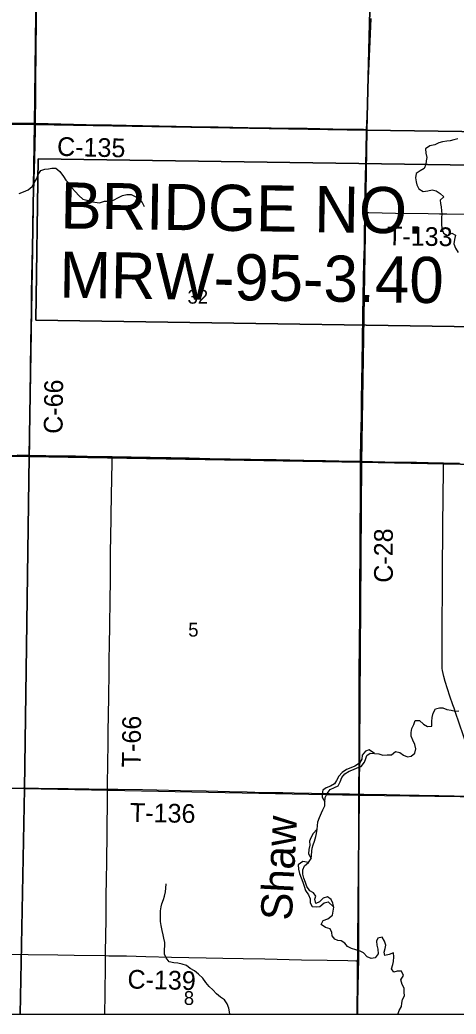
# Model space of a CAD drawing. Extents: x 0 to 34, y 0 to 22.
# Drawn here: x 3.955 to 5.278, y 14 to 17.017 of the extents above; entities that cross this region are included whole.
import ezdxf

# ---------------------------------------------------------------- set-up
doc = ezdxf.new("R2010")
doc.units = 0
for name, color, linetype in [('Default', 7, 'Continuous'), ('GM_X_City_Street', 7, 'Continuous'), ('GM_X_County_Road_Text', 7, 'Continuous'), ('GM_X_Interchange_Ramps', 7, 'Continuous'), ('GM_X_Major_River_Text', 7, 'Continuous'), ('GM_X_Minor_River', 7, 'Continuous'), ('GM_X_Minor_River_Text', 7, 'Continuous'), ('GM_X_Rail_Line', 7, 'Continuous'), ('GM_X_Section', 7, 'Continuous'), ('GM_X_Unincorporated_Location', 7, 'Continuous'), ('SH_Border', 7, 'Continuous'), ('SH_Cut_Line', 7, 'Continuous'), ('SH_Text', 7, 'Continuous')]:
    doc.layers.add(name, color=color, linetype=linetype)

msp = doc.modelspace()

# ---------------------------------------------------------------- linework, layer by layer
at = {"layer": 'Default'}
for points in [[(3.9466, 15.6957), (3.9843, 15.695), (4.0335, 15.6941), (4.077, 15.6934), (4.1236, 15.6926), (4.1951, 15.6914), (4.2351, 15.6907), (4.3504, 15.6887), (4.4125, 15.6874), (4.4684, 15.6866), (4.5305, 15.6851), (4.6547, 15.6829), (4.692, 15.6822), (4.7324, 15.6816), (4.8163, 15.68), (4.8815, 15.6788), (4.9622, 15.6771), (4.9878, 15.6767), (5.0616, 15.6752), (5.1579, 15.6733), (5.2294, 15.6716), (5.2396, 15.6714), (5.2884, 15.6704)], [(5.2884, 15.6704), (5.2396, 15.6714), (5.2294, 15.6716), (5.1579, 15.6733), (5.0616, 15.6752), (4.9878, 15.6767), (4.9622, 15.6771), (4.8815, 15.6788), (4.8163, 15.68), (4.7324, 15.6816), (4.692, 15.6822), (4.6547, 15.6829), (4.5305, 15.6851), (4.4684, 15.6866), (4.4125, 15.6874), (4.3504, 15.6887), (4.2351, 15.6907), (4.1951, 15.6914), (4.1236, 15.6926), (4.077, 15.6934), (4.0335, 15.6941), (3.9843, 15.695), (3.9466, 15.6957)], [(2.9377, 14), (7.9275, 14)]]:
    msp.add_lwpolyline(points, dxfattribs=at)
for points in [[(2.9554, 14), (3.9561, 14), (3.9687, 14.6839), (3.2537, 14.69), (2.9712, 14.7039), (2.9687, 14.7038)], [(3.9561, 14), (4.9774, 14), (4.9836, 14.6638), (3.9687, 14.6839)], [(4.9774, 14), (5.9688, 14), (5.9788, 14.6503), (4.9836, 14.6638)]]:
    msp.add_lwpolyline(points, close=True, dxfattribs=at)
at = {"layer": 'GM_X_City_Street'}
for points in [[(4.0025, 16.7029), (4.0027, 16.7213), (4.0033, 16.7679), (4.0037, 16.8145), (4.0046, 16.9356), (4.0053, 17.004), (4.0062, 17.0972), (4.0066, 17.15), (4.0072, 17.1841), (4.0076, 17.2059), (4.0077, 17.2431), (4.0078, 17.3053), (4.0084, 17.3612), (4.0087, 17.4016), (4.0091, 17.4326), (4.0093, 17.4823), (4.0097, 17.5258), (4.0103, 17.5848), (4.0105, 17.619), (4.0108, 17.6594), (4.0111, 17.7107)], [(5.0063, 16.6842), (5.0086, 16.742), (5.0115, 16.8165), (5.0144, 16.8848), (5.0161, 16.9283), (5.018, 16.9749), (5.0198, 17.0214)], [(3.9845, 15.6945), (3.9849, 15.7305), (3.9855, 15.7771), (3.9874, 15.9635), (3.9885, 16.0318), (3.9892, 16.0939), (3.99, 16.1281), (3.9904, 16.1529), (3.9906, 16.1902), (3.9915, 16.2337), (3.9921, 16.2834), (3.9937, 16.361), (3.9944, 16.4014), (3.9954, 16.4449), (3.9968, 16.4915), (3.9979, 16.5318), (3.9999, 16.597), (4.0022, 16.6809), (4.0025, 16.7029)], [(4.0025, 16.7029), (4.0098, 16.7027), (4.0408, 16.702), (4.1556, 16.6997), (4.2332, 16.6981), (4.2767, 16.697), (4.3263, 16.6961), (4.4287, 16.6943), (4.5218, 16.6925), (4.556, 16.692), (4.646, 16.6906), (4.7173, 16.6894), (4.826, 16.6877), (4.9036, 16.6864), (4.9687, 16.6853), (4.9968, 16.6849), (5.0063, 16.6842)], [(5.0014, 16.4326), (5.0023, 16.506), (5.0031, 16.5401), (5.0039, 16.5805), (5.0046, 16.6209), (5.0061, 16.6799), (5.0063, 16.6842)], [(4.988, 15.6761), (4.9881, 15.6828), (4.9891, 15.748), (4.9903, 15.8133), (4.9909, 15.8692), (4.9919, 15.9158), (4.9925, 15.9779), (4.9938, 16.0432), (4.9951, 16.1208), (4.9972, 16.2327), (4.9983, 16.2793), (4.9994, 16.329), (4.9998, 16.3694), (5.001, 16.419), (5.0014, 16.4326)], [(3.483, 15.7017), (3.5088, 15.7015), (3.5616, 15.7008), (3.6051, 15.7005), (3.6393, 15.6998), (3.6952, 15.6987), (3.8101, 15.6969), (3.8567, 15.6963), (3.9033, 15.6959), (3.9468, 15.6952), (3.9845, 15.6945)], [(3.9845, 15.6945), (4.0337, 15.6935), (4.0772, 15.6929), (4.1238, 15.6921), (4.1953, 15.6908), (4.2353, 15.6901)], [(4.2209, 14.6828), (4.2216, 14.7733), (4.2221, 14.8075), (4.2229, 14.8541), (4.2237, 14.91), (4.2244, 14.9597), (4.2255, 15.0405), (4.2261, 15.084), (4.2266, 15.1119), (4.2275, 15.1865), (4.2283, 15.2487), (4.2292, 15.3232), (4.23, 15.404), (4.2306, 15.4475), (4.2314, 15.5065), (4.233, 15.5811), (4.2338, 15.6184), (4.2351, 15.6794), (4.2352, 15.6836), (4.2353, 15.6901)], [(4.2353, 15.6901), (4.3506, 15.6882), (4.4127, 15.6869), (4.4686, 15.686), (4.5307, 15.6845), (4.655, 15.6823), (4.6922, 15.6817), (4.7326, 15.681), (4.8165, 15.6795), (4.8817, 15.6782), (4.9625, 15.6766), (4.988, 15.6761)], [(4.9831, 14.6676), (4.9831, 14.7011), (4.9834, 14.7415), (4.9835, 14.757), (4.9836, 14.7787), (4.9838, 14.8098), (4.984, 14.8719), (4.9838, 14.8843), (4.9841, 14.9153), (4.9841, 15.0458), (4.9846, 15.1111), (4.9853, 15.2261), (4.9854, 15.2882), (4.9864, 15.4156), (4.9868, 15.4871), (4.9874, 15.5554), (4.9876, 15.602), (4.9879, 15.6455), (4.988, 15.6761)], [(4.988, 15.6761), (5.0619, 15.6747), (5.1581, 15.6728), (5.2296, 15.6711), (5.2398, 15.6709)], [(5.2398, 15.6709), (5.2886, 15.6698), (5.3383, 15.6688), (5.3942, 15.6678), (5.4656, 15.6662), (5.5246, 15.6649), (5.5774, 15.6637), (5.6116, 15.663), (5.6768, 15.6617), (5.7979, 15.6591), (5.916, 15.6569), (5.9907, 15.6551)], [(3.4667, 14.6814), (3.5073, 14.6811), (3.5571, 14.6814), (3.6255, 14.6826), (3.666, 14.6832), (3.7375, 14.6841), (3.7811, 14.6847), (3.8277, 14.685), (3.9086, 14.6859), (3.9646, 14.6861), (4.0113, 14.6858), (4.1015, 14.6844), (4.1637, 14.6833), (4.2209, 14.6828)], [(4.2147, 14.1777), (4.2149, 14.1937), (4.2156, 14.2311), (4.2156, 14.2497), (4.2161, 14.2746), (4.2161, 14.2933), (4.2168, 14.3555), (4.2175, 14.4115), (4.2184, 14.4581), (4.2192, 14.5545), (4.2208, 14.654), (4.2209, 14.6828)], [(4.9822, 14.1612), (4.9823, 14.1637), (4.9823, 14.1823), (4.9823, 14.2134), (4.9824, 14.2414), (4.9825, 14.3346), (4.9827, 14.4122), (4.9825, 14.4464), (4.9823, 14.4619), (4.9823, 14.4836), (4.9826, 14.5085), (4.9829, 14.5613), (4.9831, 14.6545), (4.9831, 14.6676)], [(4.2128, 14), (4.2129, 14.0071), (4.2133, 14.0538), (4.2146, 14.1564), (4.2147, 14.1777)], [(4.2147, 14.1777), (4.225, 14.1773), (4.2374, 14.1771), (4.2778, 14.1764), (4.3368, 14.175), (4.4145, 14.1732), (4.5201, 14.1708), (4.5698, 14.1701), (4.632, 14.1688), (4.6972, 14.1675), (4.809, 14.1648), (4.8867, 14.1632), (4.9489, 14.1625), (4.9737, 14.1615), (4.9822, 14.1612)], [(4.9794, 14), (4.9801, 14.0363), (4.9808, 14.0767), (4.9817, 14.1326), (4.9822, 14.1612)]]:
    msp.add_lwpolyline(points, dxfattribs=at)
at = {"layer": 'GM_X_Interchange_Ramps'}
for points in [[(4.0025, 16.7029), (4.0027, 16.7213), (4.0033, 16.7679), (4.0037, 16.8145), (4.0046, 16.9356), (4.0053, 17.004), (4.0062, 17.0972), (4.0066, 17.15), (4.0072, 17.1841), (4.0076, 17.2059), (4.0077, 17.2431), (4.0078, 17.3053), (4.0084, 17.3612), (4.0087, 17.4016), (4.0091, 17.4326), (4.0093, 17.4823), (4.0097, 17.5258), (4.0103, 17.5848), (4.0105, 17.619), (4.0108, 17.6594), (4.0111, 17.7107)], [(3.2423, 16.7102), (3.2495, 16.71), (3.2557, 16.7098), (3.2836, 16.7097), (3.3178, 16.7094), (3.3674, 16.7088), (3.4357, 16.7082), (3.5846, 16.7073), (3.628, 16.7068), (3.7211, 16.7058), (3.7645, 16.7052), (3.8762, 16.7045), (3.9227, 16.7039), (4.0025, 16.7029)], [(3.9845, 15.6945), (3.9849, 15.7305), (3.9855, 15.7771), (3.9874, 15.9635), (3.9885, 16.0318), (3.9892, 16.0939), (3.99, 16.1281), (3.9904, 16.1529), (3.9906, 16.1902), (3.9915, 16.2337), (3.9921, 16.2834), (3.9937, 16.361), (3.9944, 16.4014), (3.9954, 16.4449), (3.9968, 16.4915), (3.9979, 16.5318), (3.9999, 16.597), (4.0022, 16.6809), (4.0025, 16.7029)], [(5.0014, 16.4326), (5.01, 16.4323), (5.0131, 16.4323), (5.0535, 16.4313), (5.0939, 16.4307), (5.1934, 16.4292), (5.2276, 16.4286), (5.2494, 16.4282), (5.3209, 16.4272), (5.3706, 16.4265), (5.4017, 16.4262), (5.4359, 16.4259), (5.4701, 16.4258), (5.5168, 16.4248), (5.6111, 16.4227)], [(4.2353, 15.6901), (4.1953, 15.6908), (4.1238, 15.6921), (4.0772, 15.6929), (4.0337, 15.6935), (3.9845, 15.6945)], [(4.2209, 14.6828), (4.2216, 14.7733), (4.2221, 14.8075), (4.2229, 14.8541), (4.2237, 14.91), (4.2244, 14.9597), (4.2255, 15.0405), (4.2261, 15.084), (4.2266, 15.1119), (4.2275, 15.1865), (4.2283, 15.2487), (4.2292, 15.3232), (4.23, 15.404), (4.2306, 15.4475), (4.2314, 15.5065), (4.233, 15.5811), (4.2338, 15.6184), (4.2351, 15.6794), (4.2352, 15.6836), (4.2353, 15.6901)], [(5.2714, 14.9283), (5.2678, 14.9387), (5.2588, 14.9651), (5.2445, 15.0095), (5.2401, 15.0244), (5.238, 15.0335), (5.2365, 15.0427), (5.2356, 15.0491), (5.2353, 15.055), (5.2349, 15.0675), (5.2353, 15.0954), (5.2356, 15.1296), (5.2356, 15.1824), (5.2357, 15.2166), (5.236, 15.257), (5.2361, 15.2818), (5.2362, 15.3129), (5.2363, 15.3471), (5.2366, 15.3906), (5.2371, 15.4279), (5.2376, 15.4745), (5.2387, 15.577), (5.2393, 15.6423), (5.2396, 15.6593), (5.2397, 15.664), (5.2398, 15.6709)], [(5.3613, 14.6602), (5.3425, 14.7179), (5.3148, 14.8004), (5.2997, 14.8445), (5.2865, 14.8827), (5.2759, 14.9151), (5.2714, 14.9283)], [(3.4667, 14.6814), (3.5073, 14.6811), (3.5571, 14.6814), (3.6255, 14.6826), (3.666, 14.6832), (3.7375, 14.6841), (3.7811, 14.6847), (3.8277, 14.685), (3.9086, 14.6859), (3.9646, 14.6861), (4.0113, 14.6858), (4.1015, 14.6844), (4.1637, 14.6833), (4.2209, 14.6828)], [(4.2147, 14.1777), (4.2149, 14.1937), (4.2156, 14.2311), (4.2156, 14.2497), (4.2161, 14.2746), (4.2161, 14.2933), (4.2168, 14.3555), (4.2175, 14.4115), (4.2184, 14.4581), (4.2192, 14.5545), (4.2208, 14.654), (4.2209, 14.6828)], [(4.2209, 14.6828), (4.2521, 14.6824), (4.3267, 14.6811), (4.3702, 14.6802), (4.4417, 14.6788), (4.5194, 14.6771), (4.5909, 14.6751), (4.6438, 14.674), (4.6904, 14.6728), (4.7525, 14.6721), (4.7867, 14.6715), (4.8396, 14.6703), (4.8676, 14.6697), (4.8927, 14.6689), (4.8958, 14.6688), (4.9145, 14.6686), (4.9549, 14.6679), (4.9766, 14.6676), (4.9831, 14.6676)], [(4.9831, 14.6676), (4.9983, 14.6676), (5.0667, 14.6663), (5.1071, 14.6656), (5.1661, 14.6644), (5.2251, 14.6631), (5.3183, 14.6613), (5.3556, 14.6604), (5.3613, 14.6602)], [(3.4578, 14.1854), (3.4678, 14.1852), (3.4709, 14.1852), (3.5143, 14.1847), (3.5485, 14.1847), (3.6292, 14.1844), (3.6696, 14.1841), (3.7131, 14.1838), (3.7907, 14.1831), (3.8435, 14.1828), (3.9243, 14.1819), (3.9801, 14.1813), (4.0702, 14.18), (4.1199, 14.1792), (4.2147, 14.1777)], [(4.2128, 14), (4.2129, 14.0071), (4.2133, 14.0538), (4.2146, 14.1564), (4.2147, 14.1777)]]:
    msp.add_lwpolyline(points, dxfattribs=at)
at = {"layer": 'GM_X_Rail_Line'}
msp.add_lwpolyline([(4.0103, 16.5951), (5.7456, 16.5696), (5.7384, 16.0796), (4.0031, 16.1052)], close=True, dxfattribs=at)
at = {"layer": 'GM_X_Section'}
for points in [[(5.2828, 16.6559), (5.2703, 16.6532), (5.2597, 16.6494), (5.2491, 16.6486), (5.2362, 16.6463), (5.2252, 16.6436), (5.2127, 16.6379), (5.1983, 16.6348), (5.185, 16.6253), (5.1862, 16.6124), (5.1893, 16.5987), (5.1867, 16.5888), (5.1856, 16.5775), (5.1807, 16.5661), (5.1682, 16.5592), (5.1565, 16.5504), (5.1543, 16.5372), (5.1562, 16.5258), (5.1585, 16.5159), (5.1646, 16.5038), (5.1779, 16.4963), (5.1916, 16.4978), (5.2052, 16.5009), (5.2177, 16.4983), (5.2295, 16.4904), (5.2402, 16.4802), (5.2292, 16.4695), (5.2304, 16.4593), (5.2327, 16.4494), (5.2335, 16.4369), (5.2339, 16.4274), (5.2336, 16.4176), (5.2329, 16.4081), (5.2333, 16.3967), (5.2348, 16.3834), (5.2394, 16.3698), (5.252, 16.363), (5.2645, 16.3691), (5.2759, 16.3639), (5.2725, 16.3502), (5.2703, 16.3373), (5.276, 16.3244), (5.284, 16.3108)], [(3.9796, 16.5006), (3.9917, 16.5112), (3.9985, 16.5226), (4.006, 16.5352), (4.0101, 16.5473), (4.0188, 16.5595), (4.0306, 16.5637), (4.0419, 16.5649), (4.0514, 16.5664), (4.0639, 16.5665), (4.0761, 16.557), (4.0876, 16.5419), (4.0944, 16.5302), (4.1047, 16.52), (4.1123, 16.5075), (4.1234, 16.4954), (4.134, 16.484), (4.1458, 16.4731), (4.1576, 16.4693), (4.1701, 16.4656), (4.1819, 16.4633), (4.1963, 16.4619), (4.2111, 16.4665), (4.2263, 16.4669), (4.2392, 16.4696), (4.2536, 16.4776), (4.2657, 16.4841), (4.2789, 16.4872), (4.2922, 16.4872), (4.3048, 16.4808), (4.3158, 16.4748), (4.3261, 16.4623), (4.3318, 16.4502)], [(3.9531, 16.4903), (3.966, 16.4949), (3.9796, 16.5006)], [(5.03, 14.791), (5.03, 14.791), (5.0437, 14.7895), (5.0555, 14.7858), (5.0691, 14.7866), (5.082, 14.787), (5.0941, 14.7965), (5.1067, 14.7935), (5.1185, 14.786), (5.1298, 14.7811), (5.1416, 14.7826), (5.1522, 14.7921), (5.1552, 14.8054), (5.1529, 14.8183), (5.146, 14.8312), (5.1414, 14.8429), (5.141, 14.8547), (5.1432, 14.8668), (5.1492, 14.879), (5.1534, 14.8911), (5.167, 14.8904), (5.1788, 14.8795), (5.191, 14.8727), (5.2042, 14.8742), (5.2038, 14.8879), (5.2049, 14.9004), (5.2083, 14.9133), (5.2151, 14.9259), (5.2276, 14.9297), (5.2374, 14.9297), (5.2492, 14.9245), (5.2625, 14.9226), (5.2762, 14.9196), (5.2856, 14.92)], [(5.03, 14.791), (5.0145, 14.8016), (5.0027, 14.7981), (4.9925, 14.7859), (4.9914, 14.7734), (4.9843, 14.7613), (4.9706, 14.7525), (4.9585, 14.7475), (4.9449, 14.7418), (4.9324, 14.733), (4.9218, 14.722), (4.9146, 14.7087), (4.909, 14.6992), (4.8969, 14.6916), (4.884, 14.6866), (4.8734, 14.6793), (4.8715, 14.668), (4.8716, 14.6581), (4.8792, 14.6445)], [(4.8792, 14.6445), (4.8811, 14.657), (4.8863, 14.6695), (4.8962, 14.6813), (4.9087, 14.6874), (4.92, 14.6931), (4.9264, 14.7045), (4.9309, 14.7175), (4.9404, 14.7289), (4.9536, 14.7369), (4.9661, 14.7426), (4.9775, 14.7472), (4.9896, 14.7514), (4.9994, 14.764), (5.0039, 14.7753), (5.0073, 14.7848), (5.0171, 14.7921), (5.03, 14.791)], [(4.8564, 14.5613), (4.8571, 14.5708), (4.8586, 14.5833), (4.8635, 14.597), (4.8699, 14.6103), (4.874, 14.6202), (4.8793, 14.6316), (4.8792, 14.6445)], [(4.8564, 14.5613), (4.8447, 14.548), (4.8375, 14.5347), (4.8334, 14.5249), (4.8338, 14.5123), (4.8312, 14.4994), (4.8301, 14.4862), (4.8377, 14.4718)], [(4.8377, 14.4718), (4.8392, 14.4813), (4.8399, 14.4945), (4.841, 14.504), (4.844, 14.5135), (4.8478, 14.5245), (4.8519, 14.5386), (4.8545, 14.5484), (4.8564, 14.5613)], [(4.8298, 14.4596), (4.8127, 14.463), (4.7991, 14.4531), (4.7999, 14.4394), (4.803, 14.4262), (4.8076, 14.4137), (4.8129, 14.4008), (4.8172, 14.3879), (4.8214, 14.3746), (4.8298, 14.3622), (4.8355, 14.3493), (4.8348, 14.3375), (4.8409, 14.3265), (4.853, 14.3251), (4.8648, 14.327), (4.878, 14.3373), (4.8902, 14.3404), (4.9069, 14.3245)], [(4.9069, 14.3245), (4.9042, 14.3366), (4.8985, 14.348), (4.8878, 14.3559), (4.8746, 14.3517), (4.8636, 14.341), (4.8519, 14.3361), (4.8495, 14.3486), (4.8522, 14.3581), (4.8457, 14.3679), (4.8339, 14.3743), (4.8255, 14.3875), (4.8205, 14.3997), (4.8163, 14.4125), (4.8132, 14.425), (4.8128, 14.4376), (4.8177, 14.4501), (4.8298, 14.4596)], [(4.8298, 14.4596), (4.8377, 14.4718)], [(4.5913, 14), (4.5909, 14.0068), (4.5886, 14.0185), (4.5836, 14.031), (4.5756, 14.0435), (4.5631, 14.0518), (4.5516, 14.062), (4.5395, 14.0733), (4.5284, 14.0835), (4.5185, 14.0964), (4.5094, 14.1093), (4.4968, 14.121), (4.4839, 14.1312), (4.4717, 14.1387), (4.4599, 14.1474), (4.447, 14.1515), (4.4341, 14.1549), (4.422, 14.1556), (4.4075, 14.1582), (4.398, 14.1703), (4.3938, 14.1824), (4.3934, 14.1957), (4.3948, 14.2075), (4.394, 14.2173), (4.391, 14.2302), (4.389, 14.2408), (4.386, 14.2533), (4.3829, 14.2685), (4.3817, 14.2814), (4.3809, 14.3003), (4.3816, 14.3129), (4.3834, 14.3254), (4.3857, 14.3349), (4.3902, 14.3482), (4.3935, 14.358), (4.3962, 14.3709), (4.3976, 14.3823), (4.3984, 14.3948)], [(5.1198, 14.0787), (5.1137, 14.0901), (5.1103, 14.1041), (5.1178, 14.1174), (5.1117, 14.1299), (5.0992, 14.1302), (5.0885, 14.1275), (5.0821, 14.1374), (5.0862, 14.1503), (5.0877, 14.1601), (5.0888, 14.1734), (5.0883, 14.1855), (5.0751, 14.1813), (5.0611, 14.1775), (5.0591, 14.1877), (5.0629, 14.1991), (5.0644, 14.209), (5.0609, 14.2211), (5.0537, 14.2332), (5.0408, 14.2309), (5.0362, 14.2214), (5.0374, 14.2093), (5.0405, 14.1968), (5.0409, 14.1831), (5.0323, 14.1709), (5.0201, 14.1686), (5.008, 14.1743), (4.9969, 14.186), (4.9863, 14.1909), (4.9738, 14.1946), (4.9605, 14.1995), (4.9487, 14.2055), (4.9403, 14.2154), (4.9289, 14.2222), (4.9194, 14.2233), (4.9099, 14.2274), (4.9019, 14.238), (4.9007, 14.2475), (4.8958, 14.2588), (4.8821, 14.2633), (4.8688, 14.2724), (4.8744, 14.2842), (4.8884, 14.2895), (4.9026, 14.3002), (4.9069, 14.3245)], [(5.102, 14), (5.1023, 14.0017), (5.1049, 14.0111), (5.1117, 14.0233), (5.1128, 14.0328), (5.115, 14.0442), (5.1207, 14.0552), (5.1202, 14.0669), (5.1198, 14.0787)]]:
    msp.add_lwpolyline(points, dxfattribs=at)
at = {"layer": 'GM_X_Unincorporated_Location'}
for points in [[(4.0116, 17.7079), (3.9996, 16.6997), (2.9891, 16.7122), (2.9907, 17.7166)], [(5.0326, 17.6924), (5.0069, 16.682), (3.9996, 16.6997), (4.0116, 17.7079)], [(6.0388, 17.6742), (6.0154, 16.6684), (5.0069, 16.682), (5.0326, 17.6924)], [(3.9996, 16.6997), (3.983, 15.6924), (2.9805, 15.7055), (2.9891, 16.7122)], [(5.0069, 16.682), (4.9903, 15.675), (3.983, 15.6924), (3.9996, 16.6997)], [(6.0154, 16.6684), (5.9927, 15.6543), (4.9903, 15.675), (5.0069, 16.682)], [(3.983, 15.6924), (3.9687, 14.6839), (3.2537, 14.69), (2.9712, 14.7039), (2.9687, 14.7038), (2.9805, 15.7055)], [(4.9903, 15.675), (4.9836, 14.6638), (3.9687, 14.6839), (3.983, 15.6924)], [(5.9927, 15.6543), (5.9788, 14.6503), (4.9836, 14.6638), (4.9903, 15.675)]]:
    msp.add_lwpolyline(points, close=True, dxfattribs=at)
at = {"layer": 'SH_Border'}
msp.add_lwpolyline([(4.0031, 16.1052), (5.7384, 16.0796), (5.7456, 16.5696), (4.0103, 16.5951)], close=True, dxfattribs=at)
at = {"layer": 'SH_Cut_Line'}
msp.add_line((2, 14), (9, 14), dxfattribs=at)
at = {"layer": 'SH_Text'}
msp.add_lwpolyline([(2.9377, 14), (8.8, 14), (8.8, 20.8), (2.9842, 20.8), (2.984, 20.7397), (2.9904, 20.3395), (2.9796, 19.7242), (2.9753, 18.7199), (2.9708, 17.6769), (2.9623, 15.7101), (2.9479, 14.7065)], close=True, dxfattribs=at)

# ---------------------------------------------------------------- texts
at = {"layer": 'GM_X_County_Road_Text'}
for s, rotation, p in [('T-133', 359.1612, (5.068, 16.3329)), ('T-66', 89.3006, (4.3207, 14.7488)), ('T-136', 358.8937, (4.2883, 14.5837))]:
    msp.add_text(s, height=0.05682, rotation=rotation, dxfattribs=at).set_placement(p)
at = {"layer": 'GM_X_Major_River_Text'}
for s, height, p in [('32', 0.04186, (4.4633, 16.1557)), ('5', 0.0419, (4.4654, 15.1454)), ('8', 0.0419, (4.452, 14.0278))]:
    msp.add_text(s, height=height, rotation=0, dxfattribs=at).set_placement(p)
at = {"layer": 'GM_X_Minor_River'}
msp.add_text('Shaw', height=0.09471, rotation=87.0782, dxfattribs=at).set_placement((4.7793, 14.2825))
at = {"layer": 'GM_X_Minor_River_Text'}
for s, rotation, p in [('C-135', 358.6237, (4.0672, 16.6044)), ('C-66', 89.3119, (4.0841, 15.7605)), ('C-28', 90, (5.0858, 15.309)), ('C-139', 358.6223, (4.2807, 14.0778))]:
    msp.add_text(s, height=0.05682, rotation=rotation, dxfattribs=at).set_placement(p)
at = {"layer": 'SH_Border'}
for s, p in [('BRIDGE NO. ', (4.0772, 16.3841)), ('MRW-95-3.40', (4.0741, 16.1741))]:
    msp.add_text(s, height=0.14, rotation=359.157, dxfattribs=at).set_placement(p)

doc.saveas('drawing.dxf')
